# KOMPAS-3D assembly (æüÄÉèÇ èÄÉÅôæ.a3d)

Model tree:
1. Эскиз:1
2. Вырезать элемент выдавливания:1
     Расстояние 1 = 146.2
3. Вырезать элемент выдавливания:3  (labels: Сплав АЛ8  ГОСТ 1583-93)
     Расстояние 1 = 146.2; Ориентация = 2; Ориентация = 2

Referenced files in D:\МОДЕЛЬ ТАНКА Т90\ДЕТАЛИ\КОРПУС\МЕТАЛЛ\КОРПУС ШТАМПОВКА\: ванна.m3d, наружняя накладка борта.m3d, ступица балансира.m3d, ступица балансира1.m3d, перемычка корпуса.m3d, дно1скос.m3d, дно2 скос .m3d, прилив.m3d, грязеочеститель.m3d, кронштейн опорного катка.m3d, упор балансира.m3d, посадка звездочки.m3d, посадка под линивец.m3d, тяга отвала.m3d, отвал.m3d, гидроамартизатор.m3d, дно корпус.m3d
Referenced files in D:\МОДЕЛЬ ТАНКА Т90\СБОРКИ\СБОРКА КОРПУСА ШТАМПОВКА\: Сборка корпус лоб.a3d, Сборка корпус верх.a3d, Сборка крышка моторного.a3d, Сборка корма верх.a3d, Сборка корма.a3d
Referenced files in D:\МОДЕЛЬ ТАНКА Т90\ДЕТАЛИ\ХОДОВАЯ\звездочка\: крышка оси звездочки.m3d
Referenced files in D:\МОДЕЛЬ ТАНКА Т90\ДЕТАЛИ\ХОДОВАЯ\Каток опорный с балансиром\: крышка оси балансира1.m3d
Referenced files in D:\МОДЕЛЬ ТАНКА Т90\ДЕТАЛИ\ОБЩИЕ ДЕТАЛИ\: крепление баков.m3d, бочка.m3d, повороты.m3d, крюк передний.m3d
Referenced files in D:\МОДЕЛЬ ТАНКА Т90\СБОРКИ\сборка фара правая\: Сборка фара правая.a3d, Сборка фара левая.a3d
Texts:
  Сборка корпус штампованный
  Сплав АЛ8  ГОСТ 1583-93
